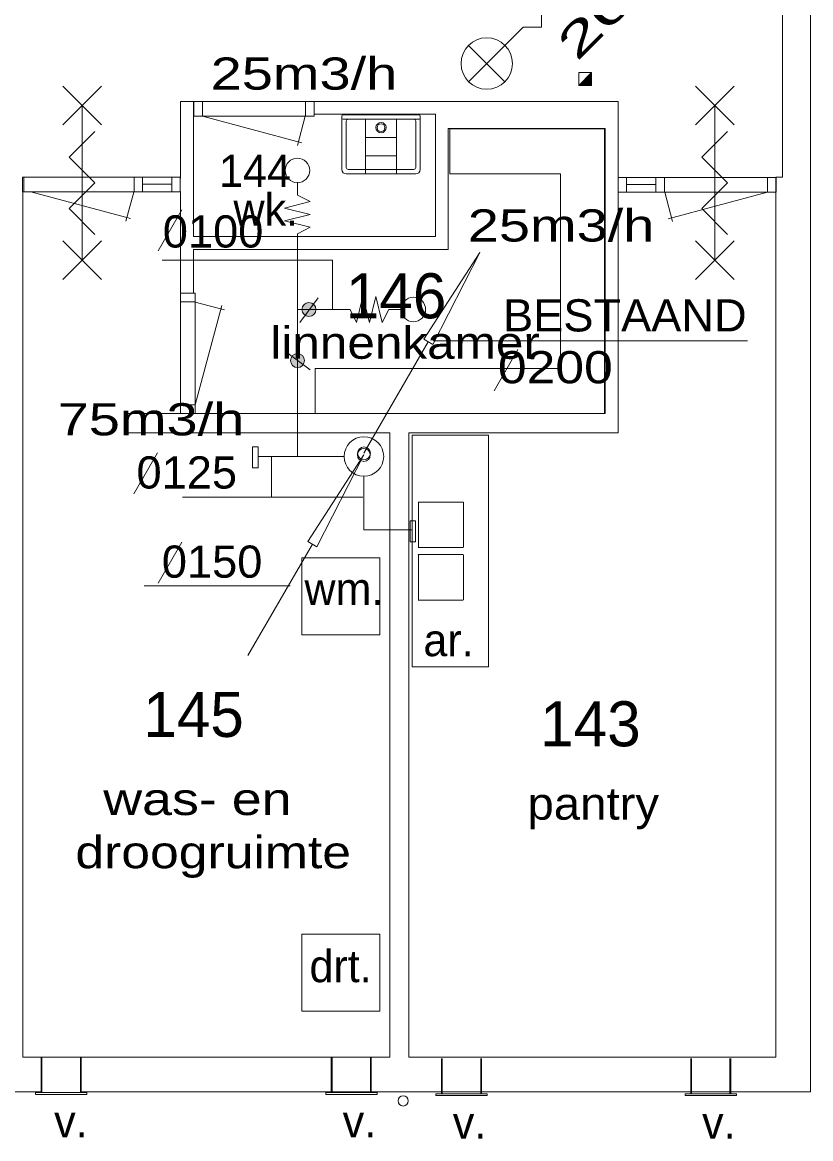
# Model space of a CAD drawing. Extents: x 295824 to 414724, y 24924 to 109024.
# Drawn here: x 326087 to 332210, y 61932 to 70606 of the extents above; entities that cross this region are included whole.
import ezdxf
from ezdxf.enums import TextEntityAlignment as Align

# ---------------------------------------------------------------- set-up
doc = ezdxf.new("R2010")
doc.units = 0
doc.header["$LTSCALE"] = 100
for name, color, linetype, lineweight in [('1', 7, 'Continuous', 13), ('24', 7, 'Continuous', 13), ('61', 7, 'Continuous', 13)]:
    doc.layers.add(name, color=color, linetype=linetype, lineweight=lineweight)

msp = doc.modelspace()

# ---------------------------------------------------------------- hatches: boundary and pattern name
at = {"layer": '24'}
for points in [[(328313.4, 68320.5, 1), (328313.4, 68429.1, 1)], [(328278.1, 67978, 1), (328169.5, 67978, 1)]]:
    msp.add_hatch(color=256, dxfattribs=at).paths.add_polyline_path(points)
at = {"layer": '61'}
msp.add_hatch(color=256, dxfattribs=at).paths.add_polyline_path([(330408.1, 70115.6), (330508.1, 70215.6), (330508.1, 70115.6)])

# ---------------------------------------------------------------- linework, layer by layer
at = {"layer": '1'}
for p, q in [((328740.2, 67257.7), (329240.2, 68123.7)), ((327839.5, 65686.4), (328339.5, 66552.4))]:
    msp.add_line(p, q, dxfattribs=at)
for points in [[(329640.2, 68816.7), (329276.2, 68102.7), (329204.2, 68144.7)], [(328739.5, 67245.4), (328375.5, 66531.4), (328303.5, 66573.4)]]:
    msp.add_lwpolyline(points, close=True, dxfattribs=at)
for centre in [(328739.5, 67245), (328740.2, 67257.4)]:
    msp.add_circle(centre, 50, dxfattribs=at)
at = {"layer": '24'}
for p, q in [((327326.6, 69150.2), (327142.3, 68830.9)), ((328223.8, 68913.4), (328223.8, 67232.7)), ((328384.2, 68466.4), (328242.6, 68274.9)), ((328582.5, 68374.9), (328223.8, 68374.9)), ((329280.4, 68131.7), (331719.9, 68131.7)), ((328132.2, 68048.9), (328323.8, 67907.2)), ((329935.2, 68063), (329750.8, 67743.7)), ((327138, 67262), (326953.6, 66942.7)), ((328586.6, 67232.7), (327924, 67232.7)), ((328023.1, 67232.3), (328023.1, 66917.6)), ((328730.7, 66917.6), (327331.3, 66917.6)), ((327325.1, 66568.2), (327140.7, 66248.9)), ((327032.5, 66227.8), (328166.4, 66227.8))]:
    msp.add_line(p, q, dxfattribs=at)
for points in [[(328223.8, 69363.4), (328223.8, 69263.4), (328323.8, 69213.4), (328123.8, 69163.4), (328323.8, 69113.4), (328123.8, 69063.4), (328323.8, 69013.4), (328223.8, 68963.4), (328223.8, 68913.4)], [(328494.8, 68380.9), (328494.8, 68758.5), (327174, 68758.5)], [(329032.5, 68374.9), (328932.5, 68374.9), (328882.5, 68274.9), (328832.5, 68474.9), (328782.5, 68274.9), (328732.5, 68474.9), (328682.5, 68274.9), (328632.5, 68374.9), (328582.5, 68374.9)], [(328740.2, 67079.1), (328740.2, 66661.9), (329114.9, 66661.9)]]:
    msp.add_lwpolyline(points, dxfattribs=at)
for points in [[(327874, 67145.2), (327917.5, 67145.2), (327917.5, 67307.5), (327874, 67307.5)], [(329098.3, 66570.2), (329141.8, 66570.2), (329141.8, 66732.5), (329098.3, 66732.5)]]:
    msp.add_lwpolyline(points, close=True, dxfattribs=at)
for centre, radius in [((328223.8, 69455.1), 95), ((329124.2, 68374.9), 95), ((328313.4, 68374.8), 54.3), ((328223.8, 67978), 54.3), ((328740.2, 67232.7), 153.6)]:
    msp.add_circle(centre, radius, dxfattribs=at)
at = {"layer": '61'}
for p, q in [((332210.1, 79160.8), (332210.1, 62296.5)), ((331990.1, 73865.8), (331990.1, 69402.2)), ((329835.6, 70144.4), (329552.8, 70427.2)), ((326700.5, 70108.8), (326400.5, 69808.8)), ((326400.5, 70108.8), (326700.5, 69808.8)), ((331615.3, 70108.8), (331315.3, 69808.8)), ((331315.3, 70108.8), (331615.3, 69808.8)), ((326550.5, 68758.8), (326550.5, 69958.8)), ((327315.1, 69991.5), (327315.1, 69391.5)), ((327415.1, 69991.5), (327315.1, 69991.5)), ((328353.5, 69991.7), (327418.2, 69991.7)), ((327486.5, 69991.7), (327486.5, 69877.7)), ((328286.5, 69991.7), (328286.5, 69877.7)), ((328353.5, 69991.7), (328353.5, 69877.7)), ((330715.1, 69991.5), (328354.4, 69991.5)), ((328354.4, 69891.5), (328354.4, 69991.5)), ((330715.1, 69391.5), (330715.1, 69991.5)), ((331465.3, 68758.8), (331465.3, 69958.8)), ((327485.7, 69877.1), (328258.4, 69670.1)), ((328284.1, 69876.5), (328223.3, 69649.6)), ((328354.4, 69891.5), (329295.1, 69891.5)), ((328567.9, 69877.7), (328567.9, 69462.7)), ((329167.9, 69887.7), (328577.9, 69887.7)), ((328577.9, 69852.7), (329167.9, 69852.7)), ((328602.9, 69477.7), (328602.9, 69837.7)), ((328752.9, 69852.7), (328752.9, 69427.7)), ((328992.9, 69852.7), (328992.9, 69427.7)), ((329142.9, 69837.7), (329142.9, 69477.7)), ((329177.9, 69462.7), (329177.9, 69877.7)), ((329295.1, 69891.5), (329295.1, 68941.5)), ((329395.1, 69781.5), (330615.1, 69781.5)), ((329407.2, 69778.6), (330608.7, 69778.6)), ((330615.1, 69781.5), (330615.1, 67566.5)), ((328752.9, 69711), (328992.9, 69711)), ((328752.9, 69569.4), (328992.9, 69569.4)), ((326097.9, 69402.7), (326097.9, 69288.7)), ((326954.4, 69402.7), (326954.4, 69288.7)), ((327021.4, 69402.7), (327021.4, 69288.7)), ((327247.4, 69402.7), (327247.4, 69288.7)), ((328602.9, 69427.7), (329142.9, 69427.7)), ((329127.9, 69462.7), (328617.9, 69462.7)), ((330780.9, 69401.2), (330780.9, 69287.2)), ((331006.9, 69401.2), (331006.9, 69287.2)), ((331073.9, 69401.2), (331073.9, 69287.2)), ((331873.9, 69401.2), (331873.9, 69287.2)), ((331940.1, 69402.2), (331940.1, 62566.5)), ((331990.1, 69402.2), (331940.1, 69402.2)), ((327247.4, 69348.6), (327021.4, 69348.6)), ((330780.9, 69347.2), (331006.9, 69347.2)), ((326090.1, 69291.5), (326090.1, 62566.5)), ((326153.6, 69288.1), (326926.4, 69081)), ((326952, 69287.5), (326891.3, 69060.6)), ((327315.1, 68501.8), (327315.1, 69291.5)), ((331076.3, 69286), (331137.1, 69059.1)), ((331874.7, 69286.6), (331102, 69079.6)), ((326700.5, 68908.8), (326400.5, 68608.8)), ((326400.5, 68908.8), (326700.5, 68608.8)), ((331615.3, 68908.8), (331315.3, 68608.8)), ((331315.3, 68908.8), (331615.3, 68608.8)), ((327314.7, 68501.2), (327428.7, 68501.2)), ((327314.7, 68501.2), (327314.7, 67566)), ((327315.1, 68501.8), (327415.1, 68501.8)), ((327314.7, 68434.2), (327428.7, 68434.2)), ((327429.4, 67633.5), (327636.4, 68406.2)), ((327430, 68431.9), (327656.8, 68371.1)), ((327314.7, 67634.2), (327428.7, 67634.2)), ((330615.1, 67566.5), (326889.8, 67566.5)), ((326889.8, 67416.5), (326889.8, 67566.5)), ((328940.1, 67416.5), (326889.8, 67416.5)), ((329161.9, 66878.8), (329511.9, 66878.8)), ((329512.8, 66877.1), (329512.8, 66527.1)), ((329511.9, 66524.7), (329161.9, 66524.7)), ((329161.9, 66470.6), (329511.9, 66470.6)), ((329512.8, 66468.9), (329512.8, 66118.9)), ((329511.9, 66116.4), (329161.9, 66116.4)), ((328940.1, 62566.5), (326090.1, 62566.5)), ((326233, 62296.5), (326233, 62566.5)), ((326239.4, 62291.6), (326239.4, 62566)), ((326538.1, 62291.6), (326538.1, 62566)), ((326543.7, 62296.5), (326543.7, 62566.5)), ((328486.7, 62296.5), (328486.7, 62566.5)), ((328493.2, 62291.6), (328493.2, 62566)), ((328791.9, 62291.6), (328791.9, 62566)), ((328797.4, 62296.5), (328797.4, 62566.5)), ((331940.1, 62566.5), (329090.1, 62566.5)), ((329341.8, 62286.6), (329341.8, 62556.6)), ((329348.3, 62281.8), (329348.3, 62556.1)), ((329647, 62281.8), (329647, 62556.1)), ((329652.5, 62286.6), (329652.5, 62556.6)), ((331278.1, 62286.6), (331278.1, 62556.6)), ((331284.5, 62281.8), (331284.5, 62556.1)), ((331583.2, 62281.8), (331583.2, 62556.1)), ((331588.8, 62286.6), (331588.8, 62556.6)), ((326233, 62296.5), (307806, 62296.5)), ((326190.1, 62291.6), (326588.4, 62291.6)), ((326190.1, 62276.5), (326190.1, 62291.6)), ((330425.5, 62296.5), (326543.7, 62296.5)), ((326588.4, 62276.5), (326588.4, 62291.6)), ((328443.9, 62291.6), (328842.2, 62291.6)), ((328443.9, 62276.5), (328443.9, 62291.6)), ((328842.2, 62276.5), (328842.2, 62291.6)), ((329299, 62281.8), (329697.3, 62281.8)), ((329299, 62266.7), (329299, 62281.8)), ((329697.3, 62266.7), (329697.3, 62281.8)), ((330425.5, 62296.5), (332210.1, 62296.5)), ((331235.2, 62281.8), (331633.5, 62281.8)), ((331235.2, 62266.7), (331235.2, 62281.8)), ((331633.5, 62266.7), (331633.5, 62281.8)), ((326190.1, 62276.5), (326588.4, 62276.5)), ((328443.9, 62276.5), (328842.2, 62276.5)), ((329299, 62266.7), (329697.3, 62266.7)), ((331235.2, 62266.7), (331633.5, 62266.7))]:
    msp.add_line(p, q, dxfattribs=at)
for points in [[(329552.8, 70144.4), (329977, 70568.7), (330118.4, 70568.7), (330118.4, 70851.5), (330401.3, 70851.5), (330401.3, 70992.9), (330542.7, 71134.3)], [(330508.1, 70215.6), (330508.1, 70115.6), (330408.1, 70115.6)], [(329295.1, 68941.5), (327415.1, 68941.5), (327415.1, 69991.5)], [(327418.2, 69991.7), (327418.2, 69877.7), (328353.5, 69877.7)], [(326650.5, 68958.8), (326450.5, 69158.8), (326650.5, 69358.8), (326450.5, 69558.8), (326650.5, 69758.8)], [(327415.1, 68501.8), (327415.1, 68841.5), (329395.1, 68841.5), (329395.1, 69781.5)], [(328361.5, 67565.7), (328361.5, 67915.7), (330267.2, 67915.7), (330267.2, 69428.6), (329407.2, 69428.6), (329407.2, 69778.6)], [(330608.7, 69778.6), (330608.7, 67565.7), (328361.5, 67565.7)], [(331565.3, 68958.8), (331365.3, 69158.8), (331565.3, 69358.8), (331365.3, 69558.8), (331565.3, 69758.8)], [(329090.1, 62566.5), (329090.1, 67416.5), (330715.1, 67416.5), (330715.1, 69291.5)], [(327314.7, 67566), (327428.7, 67566), (327428.7, 68501.2)], [(328340.1, 67416.5), (328940.1, 67416.5), (328940.1, 62566.5)], [(329113.6, 65598.8), (329708.3, 65598.8), (329708.3, 67398.8)], [(329113.6, 65598.8), (329113.6, 67398.8), (329708.3, 67398.8)], [(329162.8, 66527.1), (329162.8, 66877.1), (329161.9, 66878.8)], [(329162.8, 66118.9), (329162.8, 66468.9), (329161.9, 66470.6)]]:
    msp.add_lwpolyline(points, dxfattribs=at)
for points in [[(330508.1, 70215.6), (330408.1, 70215.6), (330408.1, 70115.6)], [(330408.1, 70115.6), (330508.1, 70215.6), (330508.1, 70115.6)], [(326087.4, 69402.7), (326087.4, 69288.7), (327313.8, 69288.7), (327313.8, 69402.7)], [(326087.4, 69402.7), (326087.4, 69288.7), (327313.8, 69288.7), (327313.8, 69402.7)], [(331940.9, 69401.2), (331940.9, 69287.2), (330714.6, 69287.2), (330714.6, 69401.2)], [(328258.6, 65846.1), (328258.6, 66446.1), (328863.1, 66446.1), (328863.1, 65846.1)], [(328258.6, 62921.9), (328258.6, 63521.9), (328863.1, 63521.9), (328863.1, 62921.9)]]:
    msp.add_lwpolyline(points, close=True, dxfattribs=at)
for centre, radius in [((329694.2, 70285.8), 200), ((328872.9, 69787.7), 40), ((328872.9, 69787.7), 30), ((329044.8, 62226.1), 40)]:
    msp.add_circle(centre, radius, dxfattribs=at)
for centre, radius, start, end in [((328577.9, 69877.7), 10, 90, 180), ((328577.9, 69862.7), 10, 180, 270), ((328617.9, 69837.7), 15, 90, 180), ((329127.9, 69837.7), 15, 0, 90), ((329167.9, 69877.7), 10, 0, 90), ((329167.9, 69862.7), 10, 270, 0), ((328617.9, 69477.7), 15, 180, 270), ((329127.9, 69477.7), 15, 270, 0), ((328602.9, 69462.7), 35, 180, 270), ((329142.9, 69462.7), 35, 270, 0)]:
    msp.add_arc(centre, radius, start, end, dxfattribs=at)

# ---------------------------------------------------------------- texts
at = {"layer": '24'}
for s, width, p in [('25m3/h', 1.3, (327549.7, 70082.9)), ('25m3/h', 1.3, (329546.6, 68902.9)), ('0100', 1.05, (327178, 68856.1)), ('BESTAAND', 1.05, (329820.8, 68204.3)), ('0200', 1.2, (329780.6, 67801.5)), ('75m3/h', 1.3, (326361.5, 67396.7)), ('0125', 1.05, (326973.6, 66983.7)), ('0150', 1.05, (327170.4, 66291))]:
    msp.add_text(s, height=250, dxfattribs=dict(at, width=width)).set_placement(p)
at = {"layer": '61', "width": 1.75}
msp.add_text('20', height=250, rotation=45, dxfattribs=at).set_placement((330393.5, 70294.3))
at = {"layer": '61'}
for s, height, p in [('144', 250, (327893.4, 69326.9)), ('146', 350, (328989.9, 68306.4)), ('145', 350, (327416.7, 65053.7)), ('143', 350, (330499.5, 64980.7))]:
    msp.add_text(s, height=height, dxfattribs=at).set_placement(p, align=Align.CENTER)
for s, p in [('wk.', (327727, 69027.2)), ('wm.', (328278.3, 66079.7)), ('ar.', (329202.1, 65681.2)), ('drt.', (328317.6, 63148.2)), ('v.', (326334.2, 61942.2)), ('v.', (328575.4, 61942.2)), ('v.', (329430.5, 61932.4)), ('v.', (331366.8, 61932.4))]:
    msp.add_text(s, height=250, dxfattribs=at).set_placement(p)
for s, width, p in [('linnenkamer', 1.15, (328012.9, 67992)), ('was- en ', 1.25, (326715.2, 64446.8)), ('pantry', 1.1, (330010.5, 64411.2)), ('droogruimte', 1.2, (326499, 64033.7))]:
    msp.add_text(s, height=250, dxfattribs=dict(at, width=width)).set_placement(p)

doc.saveas('drawing.dxf')
